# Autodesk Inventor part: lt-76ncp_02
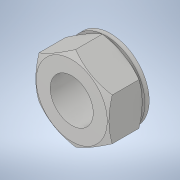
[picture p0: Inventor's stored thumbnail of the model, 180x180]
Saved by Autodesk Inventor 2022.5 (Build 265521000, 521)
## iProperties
Created: 2021-11
Part Number: lt-76ncp_02
Material: 一般
Document SubType Name: Modeling
Designer: ImaoCorp
Density: 1 g/cm^3
Appearance: 既定
Author: ImaoCorp
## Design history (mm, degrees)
feature "lt-76ncp_02"
node "ソリッド1"
